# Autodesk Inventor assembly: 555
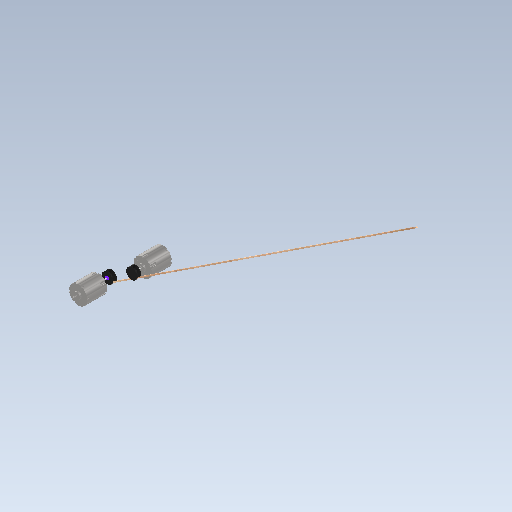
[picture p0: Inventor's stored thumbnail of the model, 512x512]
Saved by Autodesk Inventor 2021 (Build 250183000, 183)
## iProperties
Created: 2021-07
Part Number: 555
Document SubType Name: Assembly
Designer: user
Author: user
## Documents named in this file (5)
- C:\Users\user\Downloads\555.iam
- C:\Users\user\Downloads\New dc.ipt
- C:\Users\user\Downloads\New wheel.ipt
- C:\Users\user\Downloads\motor imp.ipt
- C:\Users\user\Downloads\2033333.ipt
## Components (7 placed, 4 different names)
1. New dc:1 — Mate:1
2. New wheel:1 — Mate:2, Flush:1, Angle:1, Mate:14
3. motor imp:1 — Mate:1, Mate:2
4. New dc:2 — Mate:4, Mate:6
5. New wheel:3 — Flush:1, Mate:7, Mate:9, Angle:2, Mate:13
6. motor imp:2 — Mate:4, Mate:6, Mate:7
7. 2033333:1 — Mate:9, Angle:1, Angle:2, Mate:13, Mate:14
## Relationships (11: Mate 8, Angle 2, Flush 1)
- Mate:1: New dc:1 ↔ motor imp:1
- Mate:2: New wheel:1 ↔ motor imp:1
- Mate:4: New dc:2 ↔ motor imp:2
- Mate:6: New dc:2 ↔ motor imp:2
- Flush:1: New wheel:1 ↔ New wheel:3
- Mate:7: New wheel:3 ↔ motor imp:2
- Mate:9: New wheel:3 ↔ 2033333:1
- Angle:1: New wheel:1 ↔ 2033333:1
- Angle:2: New wheel:3 ↔ 2033333:1
- Mate:13: New wheel:3 ↔ 2033333:1
- Mate:14: New wheel:1 ↔ 2033333:1
